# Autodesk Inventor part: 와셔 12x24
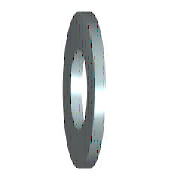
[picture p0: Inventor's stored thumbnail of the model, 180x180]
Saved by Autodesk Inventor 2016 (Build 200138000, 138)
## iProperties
IsCustomPart: 1
Created: 2012-02
Part Number: 와셔 12x24
Material: 스테인리스강
Description: 평면 와셔
Document SubType Name: Modeling
Standard: KS B 1326
Designer: mduedu
Standards Organization: KS
Language: ko-KR
Size Designation: 12x24
Categories: <MemberInstance><Categories><Category DisplayName="조임쇠" InternalName="e4da775c-781d-43d5-af7c-5136215cf5a6" Mnemonic="FSTN"><Category DisplayName="와셔" InternalN
Density: 1 g/cm^3
Appearance: 파란색 - 벽 페인트 - 광택
Author: mduedu
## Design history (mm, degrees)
sketch "스케치"
  geometry: C1 r 12 at (0, 0); C2 r 6.5 at (0, 0); 1 further point
  constraints: 2 centre point, 2 coincident
  dimensions: "d0" = 13 diameter of C2 (= SD1); "d1" = 24 diameter of C1 (= SD2)
extrude "본체" new body sketch "스케치" distance "d2" = 2.5 (= SD); taper "d3" = 0 deg
workaxis "Work Axis1"
workplane "Work Plane1"
body "Solid1"
other parameters: "SD1" = 13 [user parameter; used in 1 equation term], "SD2" = 24 [user parameter; used in 1 equation term], "SD" = 2.5 [user parameter; used in 1 equation term], "d4" = 0, "d5" = 0, "d6" = 0, "d7" = 0, "NND" = 12 [user parameter]
